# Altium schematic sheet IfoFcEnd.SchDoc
size C; Engineer: Daniel Sigg; DocumentNumber: 8; SheetNumber: 33; SheetTotal: 33
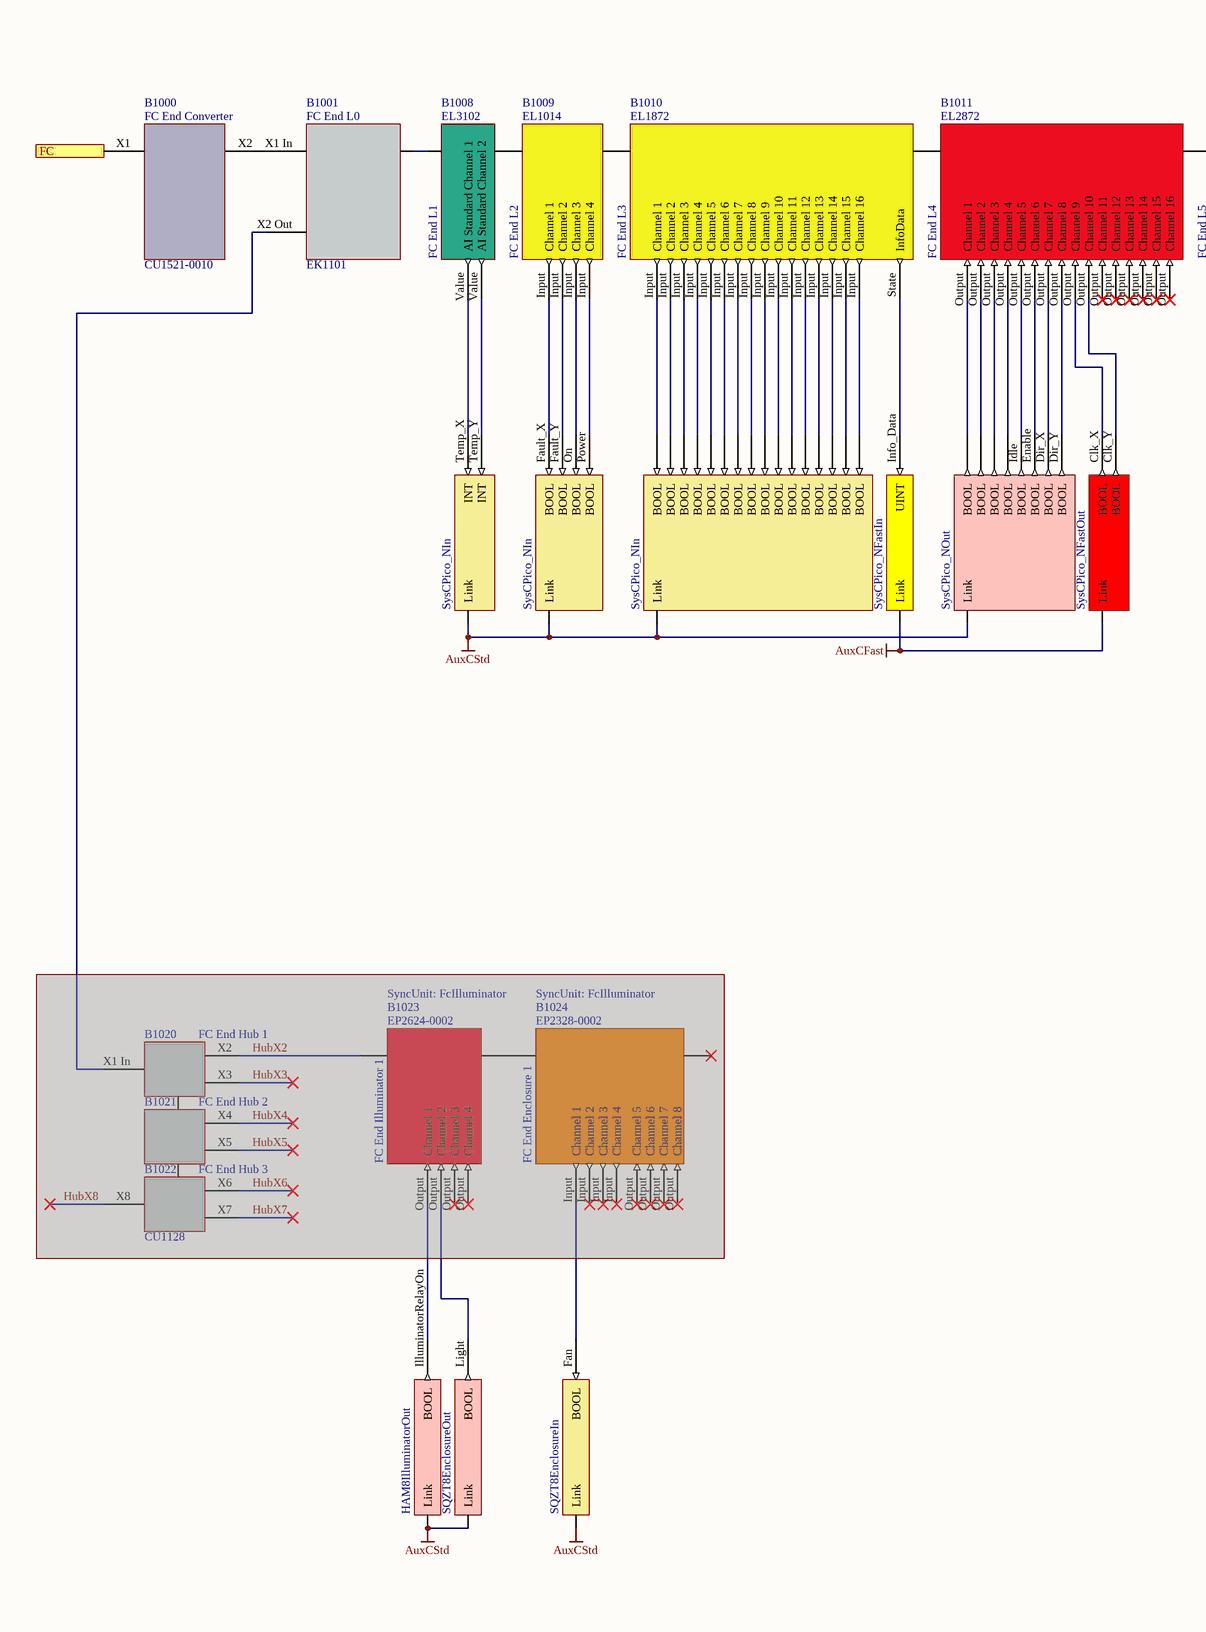
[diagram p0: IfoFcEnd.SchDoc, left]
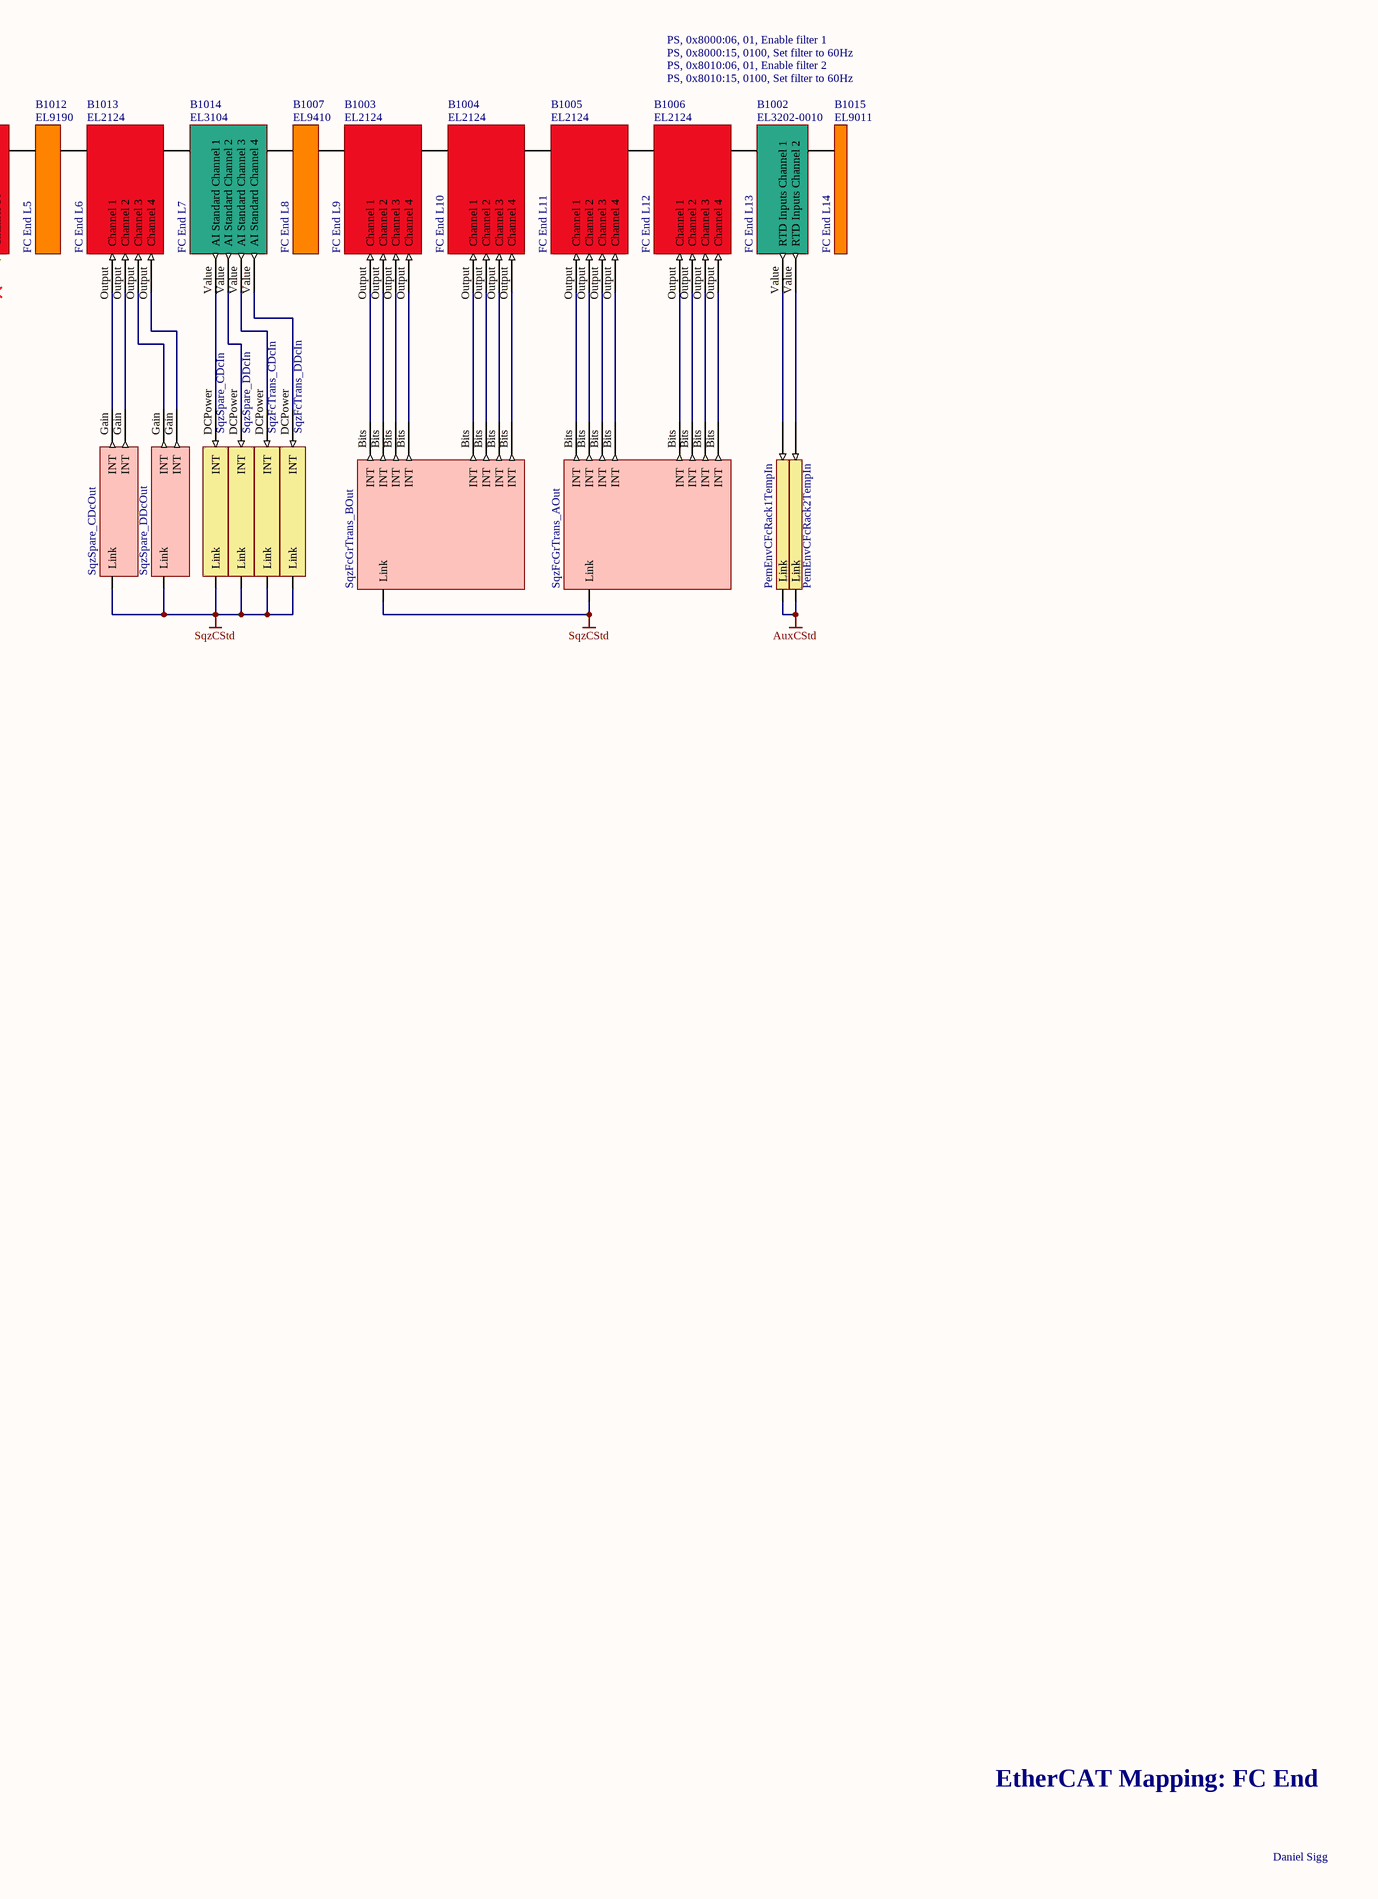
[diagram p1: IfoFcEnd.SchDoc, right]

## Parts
B1000  FC End Converter  Part Number: CU1521-0010  (mechanical)
B1001  FC End L0  Part Number: EK1101  (mechanical)
B1002  FC End L13  Part Number: EL3202-0010  Init0Cmd: PS, 0x8000:06, 01, Enable filter 1  Init1Cmd: PS, 0x8000:15, 0100, Set filter to 60Hz  Init2Cmd: PS, 0x8010:06, 01, Enable filter 2  Init3Cmd: PS, 0x8010:15, 0100, Set filter to 60Hz  (mechanical)
B1003  FC End L9  Part Number: EL2124  (mechanical)
B1004  FC End L10  Part Number: EL2124  (mechanical)
B1005  FC End L11  Part Number: EL2124  (mechanical)
B1006  FC End L12  Part Number: EL2124  (mechanical)
B1007  FC End L8  Part Number: EL9410  (mechanical)
B1008  FC End L1  Part Number: EL3102  (mechanical)
B1009  FC End L2  Part Number: EL1014  (mechanical)
B1010  FC End L3  Part Number: EL1872  (mechanical)
B1011  FC End L4  Part Number: EL2872  (mechanical)
B1012  FC End L5  Part Number: EL9190  (mechanical)
B1013  FC End L6  Part Number: EL2124  (mechanical)
B1014  FC End L7  Part Number: EL3104  (mechanical)
B1015  FC End L14  Part Number: EL9011  (mechanical)
B1020  FC End Hub 1  Part Number: CU1128  (mechanical)  (masked out: inside a compile mask, not in the netlist)
B1021  FC End Hub 2  (mechanical)  (masked out: inside a compile mask, not in the netlist)
B1022  FC End Hub 3  (mechanical)  (masked out: inside a compile mask, not in the netlist)
B1023  FC End Illuminator 1  Part Number: EP2624-0002  SyncUnit: FcIlluminator  (mechanical)  (masked out: inside a compile mask, not in the netlist)
B1024  FC End Enclosure 1  SyncUnit: FcIlluminator  Part Number: EP2328-0002  (mechanical)  (masked out: inside a compile mask, not in the netlist)
V850  PemEnvCFcRack1TempIn  (no BOM)
V851  PemEnvCFcRack2TempIn  (no BOM)
V852  SqzFcGrTrans_AOut  (no BOM)
V853  SqzFcGrTrans_BOut  (no BOM)
V854  SysCPico_NIn  (parts A,B,C of 3)  (no BOM)
V855  SysCPico_NFastIn  (no BOM)
V856  SysCPico_NOut  (no BOM)
V857  SysCPico_NFastOut  (no BOM)
V858  SqzSpare_CDcOut  (no BOM)
V859  SqzSpare_DDcOut  (no BOM)
V860  SqzSpare_CDcIn  (no BOM)
V861  SqzSpare_DDcIn  (no BOM)
V862  SqzFcTrans_CDcIn  (no BOM)
V863  SqzFcTrans_DDcIn  (no BOM)
V864  HAM8IlluminatorOut  (no BOM)
V865  SQZT8EnclosureOut  (no BOM)
V866  SQZT8EnclosureIn  (no BOM)

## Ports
FC

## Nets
AuxCFast: V855.0(Link) V857.0(Link)
AuxCStd: V850.?2(Link) V851.?2(Link) V854.0(Link) V854.1(Link) V854.2(Link) V856.0(Link) V864.0(Link) V865.?1(Link) V866.1(Link)
SqzCStd: V852.1(Link) V853.1(Link) V858.0(Link) V859.0(Link) V860.1(Link) V861.1(Link) V862.1(Link) V863.1(Link)
FC: B1000.X1(A) ; port FC
NetB1000_X2: B1000.X2(B) B1001.X1_In(A)
NetB1001_Ebus: B1001.Ebus(B) B1008.Ebus(A)
NetB1002_Ebus: B1002.Ebus(B) B1015.Ebus(A)
NetB1002_Ebus: B1002.Ebus(A) B1006.Ebus(B)  [a separate net that carries the same name]
NetB1002_Value: B1002.Value(RTD_Inputs_Channel_1) V850.?1
NetB1002_Value: B1002.Value(RTD_Inputs_Channel_2) V851.?1  [a separate net that carries the same name]
NetB1003_Ebus: B1003.Ebus(A) B1007.Ebus(B)
NetB1003_Ebus: B1003.Ebus(B) B1004.Ebus(A)  [a separate net that carries the same name]
NetB1003_Output: B1003.Output(Channel_1) V853.Bits(INT)
NetB1003_Output: B1003.Output(Channel_2) V853.Bits(INT)  [a separate net that carries the same name]
NetB1003_Output: B1003.Output(Channel_3) V853.Bits(INT)  [a separate net that carries the same name]
NetB1003_Output: B1003.Output(Channel_4) V853.Bits(INT)  [a separate net that carries the same name]
NetB1004_Ebus: B1004.Ebus(B) B1005.Ebus(A)
NetB1004_Output: B1004.Output(Channel_1) V853.Bits(INT)
NetB1004_Output: B1004.Output(Channel_2) V853.Bits(INT)  [a separate net that carries the same name]
NetB1004_Output: B1004.Output(Channel_3) V853.Bits(INT)  [a separate net that carries the same name]
NetB1004_Output: B1004.Output(Channel_4) V853.Bits(INT)  [a separate net that carries the same name]
NetB1005_Ebus: B1005.Ebus(B) B1006.Ebus(A)
NetB1005_Output: B1005.Output(Channel_1) V852.Bits(INT)
NetB1005_Output: B1005.Output(Channel_2) V852.Bits(INT)  [a separate net that carries the same name]
NetB1005_Output: B1005.Output(Channel_3) V852.Bits(INT)  [a separate net that carries the same name]
NetB1005_Output: B1005.Output(Channel_4) V852.Bits(INT)  [a separate net that carries the same name]
NetB1006_Output: B1006.Output(Channel_1) V852.Bits(INT)
NetB1006_Output: B1006.Output(Channel_2) V852.Bits(INT)  [a separate net that carries the same name]
NetB1006_Output: B1006.Output(Channel_3) V852.Bits(INT)  [a separate net that carries the same name]
NetB1006_Output: B1006.Output(Channel_4) V852.Bits(INT)  [a separate net that carries the same name]
NetB1007_Ebus: B1007.Ebus(A) B1014.Ebus(B)
NetB1008_Ebus: B1008.Ebus(B) B1009.Ebus(A)
NetB1008_Value: B1008.Value(AI_Standard_Channel_1) V854.Temp_X(INT)
NetB1008_Value: B1008.Value(AI_Standard_Channel_2) V854.Temp_Y(INT)  [a separate net that carries the same name]
NetB1009_Ebus: B1009.Ebus(B) B1010.Ebus(A)
NetB1009_Input: B1009.Input(Channel_1) V854.Fault_X(BOOL)
NetB1009_Input: B1009.Input(Channel_2) V854.Fault_Y(BOOL)  [a separate net that carries the same name]
NetB1009_Input: B1009.Input(Channel_3) V854.On(BOOL)  [a separate net that carries the same name]
NetB1009_Input: B1009.Input(Channel_4) V854.Power(BOOL)  [a separate net that carries the same name]
NetB1010_Ebus: B1010.Ebus(B) B1011.Ebus(A)
NetB1010_Input: B1010.Input(Channel_1) V854.MotorX1(BOOL)
NetB1010_Input: B1010.Input(Channel_2) V854.MotorX2(BOOL)  [a separate net that carries the same name]
NetB1010_Input: B1010.Input(Channel_3) V854.MotorX3(BOOL)  [a separate net that carries the same name]
NetB1010_Input: B1010.Input(Channel_4) V854.MotorX4(BOOL)  [a separate net that carries the same name]
NetB1010_Input: B1010.Input(Channel_5) V854.MotorX5(BOOL)  [a separate net that carries the same name]
NetB1010_Input: B1010.Input(Channel_6) V854.MotorX6(BOOL)  [a separate net that carries the same name]
NetB1010_Input: B1010.Input(Channel_7) V854.MotorX7(BOOL)  [a separate net that carries the same name]
NetB1010_Input: B1010.Input(Channel_8) V854.MotorX8(BOOL)  [a separate net that carries the same name]
NetB1010_Input: B1010.Input(Channel_9) V854.MotorY1(BOOL)  [a separate net that carries the same name]
NetB1010_Input: B1010.Input(Channel_10) V854.MotorY2(BOOL)  [a separate net that carries the same name]
NetB1010_Input: B1010.Input(Channel_11) V854.MotorY3(BOOL)  [a separate net that carries the same name]
NetB1010_Input: B1010.Input(Channel_12) V854.MotorY4(BOOL)  [a separate net that carries the same name]
NetB1010_Input: B1010.Input(Channel_13) V854.MotorY5(BOOL)  [a separate net that carries the same name]
NetB1010_Input: B1010.Input(Channel_14) V854.MotorY6(BOOL)  [a separate net that carries the same name]
NetB1010_Input: B1010.Input(Channel_15) V854.MotorY7(BOOL)  [a separate net that carries the same name]
NetB1010_Input: B1010.Input(Channel_16) V854.MotorY8(BOOL)  [a separate net that carries the same name]
NetB1010_State: B1010.State(InfoData) V855.Info_Data(UINT)
NetB1011_Ebus: B1011.Ebus(B) B1012.Ebus(A)
NetB1011_Output: B1011.Output(Channel_1) V856.MOTOR3(BOOL)
NetB1011_Output: B1011.Output(Channel_2) V856.MOTOR2(BOOL)  [a separate net that carries the same name]
NetB1011_Output: B1011.Output(Channel_3) V856.MOTOR1(BOOL)  [a separate net that carries the same name]
NetB1011_Output: B1011.Output(Channel_4) V856.MOTOR4(BOOL)  [a separate net that carries the same name]
NetB1011_Output: B1011.Output(Channel_5) V856.Idle(BOOL)  [a separate net that carries the same name]
NetB1011_Output: B1011.Output(Channel_6) V856.Enable(BOOL)  [a separate net that carries the same name]
NetB1011_Output: B1011.Output(Channel_7) V856.Dir_X(BOOL)  [a separate net that carries the same name]
NetB1011_Output: B1011.Output(Channel_8) V856.Dir_Y(BOOL)  [a separate net that carries the same name]
NetB1011_Output: B1011.Output(Channel_9) V857.Clk_X(BOOL)  [a separate net that carries the same name]
NetB1011_Output: B1011.Output(Channel_10) V857.Clk_Y(BOOL)  [a separate net that carries the same name]
NetB1012_Ebus: B1012.Ebus(B) B1013.Ebus(A)
NetB1013_Ebus: B1013.Ebus(B) B1014.Ebus(A)
NetB1013_Output: B1013.Output(Channel_1) V858.Gain(INT)
NetB1013_Output: B1013.Output(Channel_2) V858.Gain(INT)  [a separate net that carries the same name]
NetB1013_Output: B1013.Output(Channel_3) V859.Gain(INT)  [a separate net that carries the same name]
NetB1013_Output: B1013.Output(Channel_4) V859.Gain(INT)  [a separate net that carries the same name]
NetB1014_Value: B1014.Value(AI_Standard_Channel_1) V860.DCPower(INT)
NetB1014_Value: B1014.Value(AI_Standard_Channel_2) V861.DCPower(INT)  [a separate net that carries the same name]
NetB1014_Value: B1014.Value(AI_Standard_Channel_3) V862.DCPower(INT)  [a separate net that carries the same name]
NetB1014_Value: B1014.Value(AI_Standard_Channel_4) V863.DCPower(INT)  [a separate net that carries the same name]

Not connected (* = marked no-connect by the designer): B1001 X2 Out(C); V864 IlluminatorRelayOn(BOOL); V865 Light(BOOL); V866 Fan(BOOL)

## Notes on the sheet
- EtherCAT Mapping: FC End
- Daniel Sigg

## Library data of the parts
B1000 = MediaConverterFiberToCAT5: EtherCAT Media Converter; BoxType: Box; BoxNextB: WDMPTKSS; BoxPrev: TQXSIIBF; PortPrevFull: 1001/B; PortPrevShort: B 'X1'; Fullname: TIID^Filter Cavity End (EtherCAT)^FC End Converter (CU1521-0010); BoxAddr: 1002; Disabled: False
B1001 = CouplerEK1101: EtherCAT Coupler; Rail: Left; BoxNextB: HBGBFLEY; BoxPrev: PXLUFAHI; PortPrevFull: 1002/B; PortPrevShort: B 'X2'; Fullname: TIID^Filter Cavity End (EtherCAT)^FC End L0 (EK1101); BoxPorts: Junction; BoxAddr: 1003; Disabled: False
B1002 = TerminalEL3202-0010: EtherCAT Terminal EL3202-0010 2-chn Temperature Input; Rail: Left; BoxNextB: NWDBYSAB; BoxPrev: ULIEIJGL; PortPrevFull: 1014/B; PortPrevShort: B; Fullname: TIID^Filter Cavity End (EtherCAT)^FC End L0 (EK1101)^FC End L13 (EL3202-0010); BoxAddr: 1015; Disabled: False
B1003 = TerminalEL2124: EtherCAT Terminal EL2124 4-chn Digital Ouput; Rail: Left; BoxNextB: KHPMNFJU; BoxPrev: GXJCDOEX; PortPrevFull: 1010/B; PortPrevShort: B; Fullname: TIID^Filter Cavity End (EtherCAT)^FC End L0 (EK1101)^FC End L9 (EL2124); BoxAddr: 1011; Disabled: False
B1004 = TerminalEL2124: EtherCAT Terminal EL2124 4-chn Digital Ouput; Rail: Left; BoxNextB: HDSQIQHK; BoxPrev: VEPQEWPI; PortPrevFull: 1011/B; PortPrevShort: B; Fullname: TIID^Filter Cavity End (EtherCAT)^FC End L0 (EK1101)^FC End L10 (EL2124); BoxAddr: 1012; Disabled: False
B1005 = TerminalEL2124: EtherCAT Terminal EL2124 4-chn Digital Ouput; Rail: Left; BoxNextB: ULIEIJGL; BoxPrev: KHPMNFJU; PortPrevFull: 1012/B; PortPrevShort: B; Fullname: TIID^Filter Cavity End (EtherCAT)^FC End L0 (EK1101)^FC End L11 (EL2124); BoxAddr: 1013; Disabled: False
B1006 = TerminalEL2124: EtherCAT Terminal EL2124 4-chn Digital Ouput; Rail: Left; BoxNextB: DGBMPAWH; BoxPrev: HDSQIQHK; PortPrevFull: 1013/B; PortPrevShort: B; Fullname: TIID^Filter Cavity End (EtherCAT)^FC End L0 (EK1101)^FC End L12 (EL2124); BoxAddr: 1014; Disabled: False
B1007 = TerminalEL9410: EtherCAT Terminal EL9410 Power; Rail: Left; BoxNextB: VEPQEWPI; BoxPrev: MIBERBHY; PortPrevFull: 1009/B; PortPrevShort: B; Fullname: TIID^Filter Cavity End (EtherCAT)^FC End L0 (EK1101)^FC End L8 (EL9410); BoxAddr: 1010; Disabled: False
B1008 = TerminalEL3102: EtherCAT Terminal EL3102 2-chn Analog Input; Rail: Left; BoxNextB: OQWRSYUU; BoxPrev: WDMPTKSS; PortPrevFull: 1003/B; PortPrevShort: B; Fullname: TIID^Filter Cavity End (EtherCAT)^FC End L0 (EK1101)^FC End L1 (EL3102); BoxAddr: 1004; Disabled: False
B1009 = TerminalEL1014: EtherCAT Terminal EL1014 4-channel digital input terminal 24 V DC; Rail: Left; BoxNextB: DUXXGMSK; BoxPrev: HBGBFLEY; PortPrevFull: 1004/B; PortPrevShort: B; Fullname: TIID^Filter Cavity End (EtherCAT)^FC End L0 (EK1101)^FC End L2 (EL1014); BoxAddr: 1005; Disabled: False
B1010 = TerminalEL1872InfoData: EtherCAT Terminal EL1872 16-channel digital input terminal 24 V DC; Rail: Left; BoxNextB: CAWBPIQN; BoxPrev: OQWRSYUU; PortPrevFull: 1005/B; PortPrevShort: B; Fullname: TIID^Filter Cavity End (EtherCAT)^FC End L0 (EK1101)^FC End L3 (EL1872); BoxAddr: 1006; Disabled: False
B1011 = TerminalEL2872: EtherCAT Terminal EL2872 16-channel digital output terminal 24 V DC; Rail: Left; BoxNextB: RPYCVFHE; BoxPrev: DUXXGMSK; PortPrevFull: 1006/B; PortPrevShort: B; Fullname: TIID^Filter Cavity End (EtherCAT)^FC End L0 (EK1101)^FC End L4 (EL2872); BoxAddr: 1007; Disabled: False
B1012 = TerminalEL9190: EtherCAT Terminal EL9190 Supply; BoxType: TerminalPassive; Rail: Left; BoxNextB: WHVQWLXF; BoxPrev: CAWBPIQN; PortPrevShort: B; Fullname: TIID^Filter Cavity End (EtherCAT)^FC End L0 (EK1101)^FC End L5 (EL9190); Disabled: False
B1013 = TerminalEL2124: EtherCAT Terminal EL2124 4-chn Digital Ouput; Rail: Left; BoxNextB: MIBERBHY; BoxPrev: RPYCVFHE; PortPrevFull: 1007/B; PortPrevShort: B; Fullname: TIID^Filter Cavity End (EtherCAT)^FC End L0 (EK1101)^FC End L6 (EL2124); BoxAddr: 1008; Disabled: False
B1014 = TerminalEL3104: EtherCAT Terminal EL3104 4-chn Analog Input; Rail: Left; BoxNextB: GXJCDOEX; BoxPrev: WHVQWLXF; PortPrevFull: 1008/B; PortPrevShort: B; Fullname: TIID^Filter Cavity End (EtherCAT)^FC End L0 (EK1101)^FC End L7 (EL3104); BoxAddr: 1009; Disabled: False
B1015 = TerminalEL9011: EtherCAT Terminal EL9011 End; BoxType: TerminalPassive; Rail: Left; BoxPrev: DGBMPAWH; PortPrevShort: B; Fullname: TIID^Filter Cavity End (EtherCAT)^FC End L0 (EK1101)^FC End L14 (EL9011); Disabled: False
B1020 = HubCU1128: EtherCAT Hub; BoxType: Box; BoxPorts: Junction; Disabled: False
B1021 = HubCU1128-B: EtherCAT Hub subpart B; Part Number: CU1128-0001; BoxType: Box; BoxPorts: Junction; Disabled: False
B1022 = HubCU1128-C: EtherCAT Hub subpart C; Part Number: CU1128-0002; BoxType: Box; BoxPorts: Junction; Disabled: False
B1023 = BoxEP2624-0002: EtherCAT Box EP2624-0002 4-channel relay output 25 V AC/30 V DC; Disabled: False
B1024 = BoxEP2328-0002: EtherCAT Box EP2328-0002 4 x digital input and 4 x digital output 24 V DC; Disabled: False
V850 V851 = VariableInINT: INT; PLC: H1AuxCorner; Task: AuxCStd; Instance: H1AuxCorner Instance
V852 V853 = IscWhitening_WhiteningBitsOutStruct: WhiteningBitsOutStruct; BoxType: Variable; Instance: H1SqzCorner Instance; PLC: H1SqzCorner; Task: SqzCStd
V854 = Picomotor_PicomotorInStruct: PicomotorInStruct; BoxType: Variable; Instance: H1AuxCorner Instance; PLC: H1AuxCorner; Task: AuxCStd
V855 = Picomotor_PicomotorFastInStruct: PicomotorFastInStruct; BoxType: Variable; Instance: H1AuxCorner Instance; PLC: H1AuxCorner; Task: AuxCFast
V856 = Picomotor_PicomotorOutStruct: PicomotorOutStruct; BoxType: Variable; Instance: H1AuxCorner Instance; PLC: H1AuxCorner; Task: AuxCStd
V857 = Picomotor_PicomotorFastOutStruct: PicomotorFastOutStruct; BoxType: Variable; Instance: H1AuxCorner Instance; PLC: H1AuxCorner; Task: AuxCFast
V858 V859 = DCPower_DCPowerOutStruct: DCPowerOutStruct; BoxType: Variable; Instance: H1SqzCorner Instance; PLC: H1SqzCorner; Task: SqzCStd
V860-V863 = DCPower_DCPowerInStruct: DCPowerInStruct; BoxType: Variable; Instance: H1SqzCorner Instance; PLC: H1SqzCorner; Task: SqzCStd
V864 = Illuminator_IlluminatorOutStruct: IlluminatorOutStruct; BoxType: Variable; Instance: H1AuxCorner Instance; PLC: H1AuxCorner; Task: AuxCStd
V865 = Enclosure_EnclosureOutStruct: EnclosureOutStruct; BoxType: Variable; Instance: H1AuxCorner Instance; PLC: H1AuxCorner; Task: AuxCStd
V866 = Enclosure_EnclosureInStruct: EnclosureInStruct; BoxType: Variable; Instance: H1AuxCorner Instance; PLC: H1AuxCorner; Task: AuxCStd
